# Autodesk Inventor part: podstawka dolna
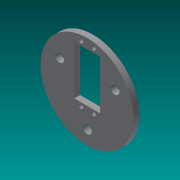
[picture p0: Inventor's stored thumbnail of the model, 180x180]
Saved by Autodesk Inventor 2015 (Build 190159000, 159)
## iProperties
Created: 2016-02
Part Number: podstawka dolna
Material: Generic
Document SubType Name: Modeling
Designer: Rafał
Density: 1 g/cm^3
Appearance: Default
Author: Rafał
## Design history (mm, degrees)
sketch "Sketch1" dims "d9" = 55
  geometry: L1 (0, 0)-(5.4, 0); L2 (5.4, 0)-(5.4, -13.4); L3 (5.4, 0)-(5.4, 35.4); L4 (0, 0)-(0, 11.296); L5 (0, 0)-(11, 0); L6 (11, 0)-(11, 31.5); L7 (11, 0)-(11, -10.5); L8 (11, -10.5)-(1, -10.5); L9 (11, 31.5)-(1, 31.5); L10 (-11, 31.5)-(1, 31.5); L11 (-11, 0)-(-11, 31.5); L12 (-11, 0)-(-11, -10.5); L13 (-11, -10.5)-(1, -10.5); L14 (0, 0)-(0, -35.729); C1 r 2 at (5.4, 35.4); C2 r 2 at (5.4, -13.4); C3 r 2 at (-5.4, 35.4); C4 r 2 at (-5.4, -13.4); C5 r 40 at (0, 0); C6 r 4 at (0, -27.5); C7 r 4 at (23.816, 13.75); C8 r 4 at (-23.816, 13.75); 3 further points
  constraints: 28 end point, 8 centre point, 7 symmetric about line, 6 coincident, 4 vertical, 3 horizontal, 3 perpendicular, 1 point on line, 1 vertical alignment, 11 other
  dimensions: "d0" = 5.4 distance of L1.start L1.end; "d1" = 13.4 distance of L1.end L2.end; "d2" = 35.4 distance of L1.end L3.end; "d3" = 4 diameter of C1; "d4" = 4 diameter of C2; "d5" = 11 distance of L1.start L5.end; "d6" = 31.5 distance of L5.end L6.end; "d7" = 10.5 distance of L5.end L7.end; "d8" = 80 diameter of C5; "d10" = 8 diameter of C6; "d13" = 360 deg dimension on L1.start C6.centre (derived)
extrude "Extrusion1" new body sketch "Sketch1" distance "d15" = 5; taper "d16" = 0 deg
body "Solid1"
